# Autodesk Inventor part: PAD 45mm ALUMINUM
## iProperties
Created: 2007-03
Part Number: PAD 45mm ALUMINUM
Document SubType Name: Modeling
Designer: Andy Moles
Material: Aluminum-6061
Mass: 43.8341 g
Surface Area: 55.7467 cm^2
Volume: 16.1749 cm^3
Density: 2.71 g/cm^3
Author: Andy Moles
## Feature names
1. Revolution1
